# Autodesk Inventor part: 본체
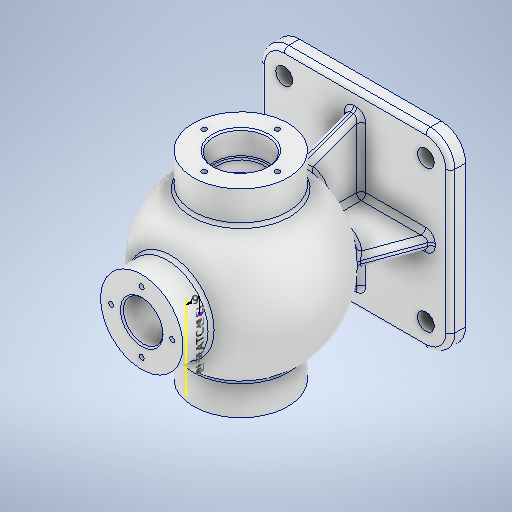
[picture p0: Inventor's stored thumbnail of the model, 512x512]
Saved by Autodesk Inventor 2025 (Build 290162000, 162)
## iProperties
Created: 2025-08
Part Number: 본체
Material: 알루미늄 6061
Document SubType Name: Sheet Metal
Designer: infra02
Density: 2.7 g/cm^3
Sheet Metal Rule: 기본값_mm
Appearance: 알루미늄 - 평지
Mass: 1526.65 g
Surface Area: 1172.5 cm^2
Volume: 565.426 cm^3
Author: infra02
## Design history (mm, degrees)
sketch "스케치1"
  geometry: L1 (-62.5, 62.5)-(62.5, 62.5); L2 (62.5, 62.5)-(62.5, -62.5); L3 (62.5, -62.5)-(-62.5, -62.5); L4 (-62.5, -62.5)-(-62.5, 62.5); L5 (-62.5, 62.5)-(62.5, -62.5); L6 (62.5, 62.5)-(-62.5, -62.5); L7 (-46.5, 46.5)-(46.5, 46.5); L8 (46.5, 46.5)-(46.5, -46.5); L9 (46.5, -46.5)-(-46.5, -46.5); L10 (-46.5, -46.5)-(-46.5, 46.5); L11 (-46.5, 46.5)-(46.5, -46.5); L12 (46.5, 46.5)-(-46.5, -46.5); C1 r 5.5 at (-46.5, 46.5); C2 r 5.5 at (46.5, 46.5); C3 r 5.5 at (-46.5, -46.5); C4 r 5.5 at (46.5, -46.5); 5 further points
  constraints: 24 end point, 7 coincident, 4 centre point, 4 midpoint, 4 parallel, 2 horizontal, 2 perpendicular, 1 point on line
  dimensions: "d0" = 125 distance of L2.end L3.end; "d1" = 125 distance of L1.end L2.end; "d2" = 93 distance of L8.end L9.end; "d3" = 93 distance of L7.end L8.end; "d4" = 11 diameter of C1; "d5" = 11 diameter of C2; "d6" = 11 diameter of C3; "d7" = 11 diameter of C4; "d8" = 16 distance from line of L4 C3.centre
extrude "돌출1" new body sketch "스케치1" stored distance "d9" = 10; taper "d10" = 0 deg
node "작업 평면1"
sketch "스케치3"
  geometry: L1 (0, 54)-(0, -54); A1 r 54 centre (0, 0) between (0, 54) and (0, -54); 1 further point
  constraints: 2 end point, 2 point on circle, 1 centre point, 1 coincident, 1 vertical
  dimensions: "d12" = 108 diameter of A1; "d13" = 108 distance of L1.start L1.end
revolve "회전1" sketch "스케치3" stored, may be unused: angle "d14" = 90 deg
sketch "스케치5"
  geometry: L1 (-62.5, -5)-(-62.5, 5) reference; L2 (62.5, 5)-(-62.5, 5) reference; L3 (62.5, 5)-(62.5, -5) reference; L4 (-62.5, -5)-(62.5, -5) reference; L5 (62.5, 5)-(-62.5, 5) reference; L6 (50.5, 5)-(30.869, 58.937); L7 (-50.5, 5)-(-30.789, 59.154); L8 (50.5, 5)-(-50.5, 5); L9 (30.869, 58.937)-(-30.869, 58.937); 3 further points
  constraints: 8 end point, 3 point on line, 1 collinear, 1 parallel
  dimensions: "d15" = 20 deg angle of L6 L3; "d16" = 20 deg angle of L1 L7; "d17" = 12 distance of L6.start L2.start; "d18" = 12 distance of L1.end L7.start
extrude "돌출2" join sketch "스케치5" stored distance "d19" = 8; taper "d20" = 0 deg
sketch "스케치6"
  geometry: L1 (62.5, -5)-(62.5, 5) reference; L2 (-62.5, 5)-(62.5, 5) reference; L3 (-62.5, -5)-(-62.5, 5) reference; L4 (62.5, -5)-(-62.5, -5) reference; L5 (-50.5, 5)-(-30.386, 60.262); L6 (52, 5)-(52, -5) reference; L7 (50.5, 5)-(26.621, 70.608); L8 (50.5, 5)-(-50.5, 5); L9 (26.621, 70.608)-(-26.621, 70.608); L10 (-26.621, 70.608)-(-37.385, 41.034); A1 r 54 centre (0, 80) between (4, 26.148) and (-4, 26.148) reference; 3 further points
  constraints: 10 end point, 2 point on line, 1 horizontal, 1 point on circle
  dimensions: "d21" = 20 deg angle of L3 L5; "d23" = 12 distance of L5.start L2.start; "d24" = 12 distance of L7.start L1.end; "d25" = 0 distance from line of L2 L7.start; "d26" = 20 deg angle of L7 L1
extrude "돌출3" join sketch "스케치6" stored distance "d27" = 8; taper "d28" = 0 deg
node "작업 평면2"
sketch "스케치9"
  geometry: L1 (-4, 41.186)-(-4, 26.297) reference; L2 (-37.329, 41.186)-(-37.329, 41.186) reference; L3 (-4, 26.297)-(-4, 41.186) reference; L4 (4, 41.186)-(4, 26.297) reference; L5 (37.329, 41.186)-(37.329, 41.186) reference; L6 (4, 26.297)-(4, 41.186) reference; C1 r 31 at (0, 80); A1 r 53.852 centre (0, 80) between (-37.329, 41.186) and (-4, 26.297) reference; A2 r 53.852 centre (0, 80) between (-37.329, 41.186) and (-4, 26.297) reference; A3 r 53.852 centre (0, 80) between (4, 26.297) and (37.329, 41.186) reference; A4 r 53.852 centre (0, 80) between (4, 26.297) and (37.329, 41.186) reference; 3 further points; 2 other entities
  constraints: 1 centre point, 1 coincident, 2 other
  dimensions: "d30" = 62 diameter of C1
extrude "돌출4" join sketch "스케치9" distance "d31" = 15; taper "d32" = 0 deg
feature "면 삭제1"
feature "면 삭제2"
node "작업 평면3"
sketch "스케치10"
  geometry: C1 r 27 at (0, 0); 1 further point
  constraints: 1 centre point, 1 coincident
  dimensions: "d34" = 54 diameter of C1
extrude "돌출5" join sketch "스케치10" distance "d35" = 20; taper "d36" = 0 deg
sketch "스케치11"
  geometry: C1 r 13 at (0, 0); 1 further point
  constraints: 1 centre point, 1 coincident
  dimensions: "d37" = 26 diameter of C1
extrude "돌출6" cut sketch "스케치11" distance "d38" = 35.5; taper "d39" = 0 deg
sketch "스케치12"
  geometry: C1 r 17.5 at (0, 0); C2 r 31 at (0, 0) reference; 1 further point
  constraints: 1 centre point, 1 concentric
  dimensions: "d40" = 35 diameter of C1
extrude "돌출7" cut sketch "스케치12" distance "d41" = 155; taper "d42" = 0 deg
sketch "스케치16"
  geometry: L1 (65, 97.5)-(65, 62.5) reference; L2 (65, 80)-(-65, 80); L3 (-65, 62.5)-(-65, 97.5) reference; L4 (65, 80)-(49, 80); L5 (65, 97.5)-(-65, 97.5) reference; L6 (49, 80)-(49, 95); L7 (49, 95)-(28.624, 95); L8 (28.624, 95)-(28.624, 80); L9 (47.915, 80)-(28.624, 80); L10 (49, 95)-(28.624, 95); L11 (28.624, 95)-(28.624, 97.5); L12 (28.624, 97.5)-(49, 97.5); L13 (49, 97.5)-(49, 95); 3 further points
  constraints: 20 end point, 5 point on line, 3 perpendicular, 2 horizontal, 2 midpoint, 2 parallel, 1 collinear
  dimensions: "d65" = 16 distance of L2.start L4.end; "d66" = 15 distance of L4.end L6.end; "d67" = 20.3763 distance between parallel lines of L6 L8
revolve "회전3" sketch "스케치16" stored, may be unused: angle "d68" = 90 deg
sketch "스케치13"
  geometry: L1 (-27, 126.765)-(27, 126.765) reference; L2 (-44.215, 49)-(-44.215, 111) reference; L3 (44.215, 111)-(44.215, 49) reference; L4 (-4, 26.297)-(-4, 41.186) reference; L5 (4, 41.186)-(4, 26.297) reference; L6 (37.329, 41.186)-(37.329, 41.186) reference; L7 (4, 26.297)-(4, 41.186) reference; L8 (-4, 41.186)-(-4, 26.297) reference; L9 (-37.329, 41.186)-(-37.329, 41.186) reference; L10 (-44, 80)-(44, 80); L11 (-65, 49)-(-65, 111) reference; L12 (88, 80)-(-90.5, 80) reference; A1 r 53.852 centre (0, 80) between (-37.329, 41.186) and (-4, 26.297) reference; A2 r 53.852 centre (0, 80) between (4, 26.297) and (37.329, 41.186) reference; A3 r 53.852 centre (0, 80) between (4, 26.297) and (37.329, 41.186) reference; A4 r 53.852 centre (0, 80) between (-37.329, 41.186) and (-4, 26.297) reference; A5 r 44 centre (0, 80) between (-44, 80) and (44, 80); 4 further points; 2 other entities
  constraints: 2 end point, 2 point on circle, 1 centre point, 1 coincident, 1 midpoint, 1 perpendicular, 1 point on line, 2 other
  dimensions: "d43" = 88 diameter of A5
revolve "회전2" sketch "스케치13" stored, may be unused: angle "d44" = 90 deg
sketch "스케치14"
  geometry: C1 r 31 at (0, 0) reference; A1 r 24 centre (0, 0) between (0, 24) and (-24, 0); 3 further points
  constraints: 4 point on circle, 1 centre point, 1 concentric
  dimensions: "d45" = 48 diameter of A1
hole "구멍1" sketch "스케치14" at (0, 24), (-24, 0), (0, -24), (24, 0) diameter "d46" = 3.242; stored, may be unused: countersink angle "d50" = 90 deg, drill point angle "d52" = 118 deg; dims "d47" = 12, "d48" = 4, "d49" = 2, "d51" = 15
sketch "스케치15"
  geometry: L1 (15, -41.364)-(-15, -41.364) reference; L2 (-15, 41.364)-(15, 41.364) reference; C1 r 13 at (0, 0) reference; A1 r 20 centre (0, 0) between (20, 0) and (0, 20); 3 further points
  constraints: 4 point on circle, 1 centre point, 1 coincident
  dimensions: "d53" = 40 diameter of A1
hole "구멍2" sketch "스케치15" at (20, 0), (0, 20), (-20, 0), (0, -20) diameter "d54" = 3.242; stored, may be unused: countersink angle "d58" = 90 deg, drill point angle "d60" = 118 deg; dims "d55" = 9, "d56" = 4, "d57" = 2, "d59" = 11
fillet "모깎기1" dims "d61" = 3
fillet "모깎기2" dims "d62" = 3
fillet "모깎기3" dims "d63" = 16
fillet "모깎기4" dims "d64" = 3
fillet "모깎기5" dims "d69" = 3
chamfer "모따기1" distance "d70" = 1; stored, may be unused: second distance "d71" = 2, angle "d72" = 45 deg
chamfer "모따기2" distance "d73" = 1; stored, may be unused: second distance "d74" = 2, angle "d75" = 45 deg
fillet "모깎기6" dims "d76" = 0.6
chamfer "모따기3" distance "d77" = 1; stored, may be unused: second distance "d78" = 2, angle "d79" = 45 deg
fillet "모깎기7" dims "d80" = 0.6
fillet "모깎기8" dims "d81" = 3
node "작업 평면5"
sketch "스케치17"
  geometry: L1 (-14.282, 140.462)-(14.449, 140.462); L2 (14.449, 140.462)-(14.449, 131.538); L3 (14.449, 131.538)-(-14.282, 131.538); L4 (-14.282, 131.538)-(-14.282, 140.462); L5 (-27, 145)-(27, 145) reference; 2 further points
  constraints: 1 midpoint, 2 other
  dimensions: "d86" = 9 distance from line of L5 point (14.449, 136)
feature "Ќ耀Ў耀А耀В耀Д耀Ж耀И耀К耀" dims "d0" = 125, "d1" = 125, "d2" = 93, "d3" = 93, "d4" = 11, "d5" = 11, "d6" = 11, "d7" = 11, "d8" = 16, "d9" = 10, "d10" = 0, "d11" = -85, "d12" = 108, "d13" = 108, "d14" = 90 deg, "d15" = 20 deg, "d16" = 20 deg, "d17" = 12, "d18" = 12, "d19" = 8, "d20" = 0, "d21" = 20 deg, "d23" = 12, "d24" = 12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
node "솔리드1"
mirror "미러1"
mirror "미러3"
mirror "미러2"
node "투영된 루프1"
node "투영된 루프2"
node "투영된 루프4"
node "투영된 루프5"
node "투영된 루프6"
feature "A9D066F2-1C7D-4E18-AEED-F7BC21143FA4" dims "d46" = 3.242, "d47" = 12, "d48" = 4, "d49" = 2, "d50" = 90 deg, "d51" = 15, "d52" = 118 deg
